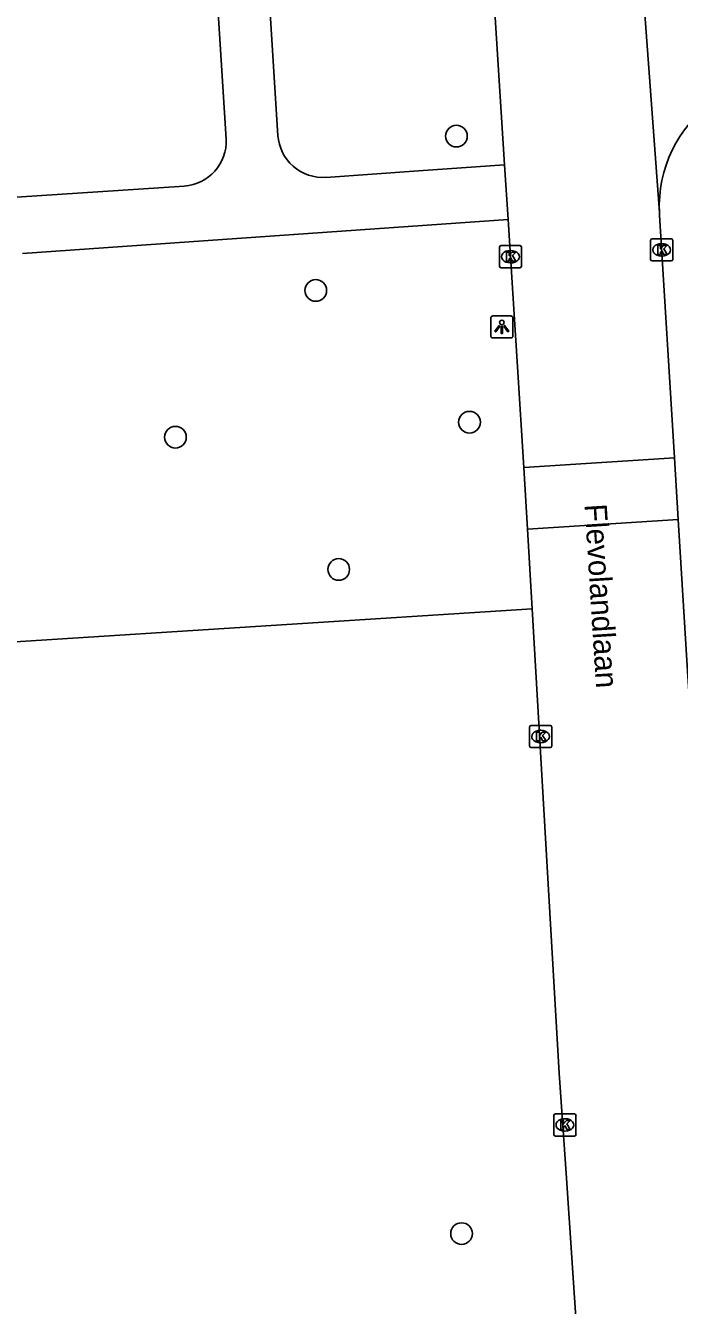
# Model space of a CAD drawing. Extents: x 159689 to 160786, y 387323 to 388339.
# Drawn here: x 160199.1 to 160228.6, y 387891.1 to 387948.8 of the extents above; entities that cross this region are included whole.
import ezdxf

# ---------------------------------------------------------------- set-up
doc = ezdxf.new("R2010")
doc.units = 0
for name, color, linetype in [('IMGEO_Boom', 7, 'Continuous'), ('IMGEO_Groenvoorziening', 7, 'Continuous'), ('IMGEO_Kolk', 7, 'Continuous'), ('IMGEO_Lichtpunt', 7, 'Continuous'), ('IMGEO_Openbare_ruimte_label', 7, 'Continuous'), ('IMGEO_Rijbaan_lokaal_open', 7, 'Continuous'), ('IMGEO_Voetpad_open', 7, 'Continuous')]:
    doc.layers.add(name, color=color, linetype=linetype)

msp = doc.modelspace()

# ---------------------------------------------------------------- linework, layer by layer
at = {"layer": 'IMGEO_Boom'}
for centre in [(160218.549, 387943.853), (160212.205, 387936.889), (160219.138, 387930.946), (160205.876, 387930.269), (160213.238, 387924.301), (160218.781, 387894.331)]:
    msp.add_circle(centre, 0.489, dxfattribs=at)
at = {"layer": 'IMGEO_Groenvoorziening'}
msp.add_lwpolyline([(160221.967, 387922.53), (160198.415, 387921.014), (160192.67, 387937.221)], dxfattribs=at)
at = {"layer": 'IMGEO_Kolk'}
for p, q in [((160227.379, 387939.219), (160228.231, 387939.219)), ((160220.484, 387937.987), (160220.484, 387938.839)), ((160220.559, 387938.913), (160221.411, 387938.913)), ((160220.972, 387938.693), (160220.997, 387938.693)), ((160221.485, 387938.839), (160221.485, 387937.987)), ((160227.304, 387938.293), (160227.304, 387939.145)), ((160227.792, 387938.999), (160227.817, 387938.999)), ((160228.305, 387939.145), (160228.305, 387938.293)), ((160220.995, 387938.133), (160220.97, 387938.133)), ((160228.231, 387938.219), (160227.379, 387938.219)), ((160227.815, 387938.439), (160227.79, 387938.439)), ((160221.411, 387937.913), (160220.559, 387937.913)), ((160221.919, 387917.262), (160222.771, 387917.262)), ((160221.844, 387916.336), (160221.844, 387917.188)), ((160222.332, 387917.042), (160222.357, 387917.042)), ((160222.845, 387917.188), (160222.845, 387916.336)), ((160222.771, 387916.262), (160221.919, 387916.262)), ((160222.355, 387916.482), (160222.33, 387916.482)), ((160222.94, 387898.81), (160222.94, 387899.662)), ((160223.015, 387899.736), (160223.867, 387899.736)), ((160223.428, 387899.516), (160223.453, 387899.516)), ((160223.941, 387899.662), (160223.941, 387898.81)), ((160223.867, 387898.736), (160223.015, 387898.736)), ((160223.451, 387898.956), (160223.426, 387898.956))]:
    msp.add_line(p, q, dxfattribs=at)
for points in [[(160227.379, 387939.219), (160228.231, 387939.219)], [(160220.484, 387937.987), (160220.484, 387938.839)], [(160220.559, 387938.913), (160221.411, 387938.913)], [(160220.805, 387938.613), (160220.928, 387938.613), (160220.928, 387938.462), (160221.058, 387938.613), (160221.222, 387938.613), (160221.076, 387938.462), (160221.229, 387938.213), (160221.077, 387938.213), (160220.992, 387938.377), (160220.928, 387938.31), (160220.928, 387938.213), (160220.805, 387938.213), (160220.805, 387938.613)], [(160221.485, 387938.839), (160221.485, 387937.987)], [(160227.304, 387938.293), (160227.304, 387939.145)], [(160227.625, 387938.919), (160227.748, 387938.919), (160227.748, 387938.768), (160227.878, 387938.919), (160228.042, 387938.919), (160227.896, 387938.768), (160228.049, 387938.519), (160227.897, 387938.519), (160227.812, 387938.683), (160227.748, 387938.616), (160227.748, 387938.519), (160227.625, 387938.519), (160227.625, 387938.919)], [(160228.305, 387939.145), (160228.305, 387938.293)], [(160228.231, 387938.219), (160227.379, 387938.219)], [(160221.411, 387937.913), (160220.559, 387937.913)], [(160221.919, 387917.262), (160222.771, 387917.262)], [(160221.844, 387916.336), (160221.844, 387917.188)], [(160222.165, 387916.962), (160222.288, 387916.962), (160222.288, 387916.811), (160222.418, 387916.962), (160222.582, 387916.962), (160222.436, 387916.811), (160222.589, 387916.562), (160222.437, 387916.562), (160222.352, 387916.726), (160222.288, 387916.659), (160222.288, 387916.562), (160222.165, 387916.562), (160222.165, 387916.962)], [(160222.845, 387917.188), (160222.845, 387916.336)], [(160222.771, 387916.262), (160221.919, 387916.262)], [(160222.94, 387898.81), (160222.94, 387899.662)], [(160223.015, 387899.736), (160223.867, 387899.736)], [(160223.261, 387899.436), (160223.384, 387899.436), (160223.384, 387899.285), (160223.514, 387899.436), (160223.678, 387899.436), (160223.532, 387899.285), (160223.685, 387899.036), (160223.533, 387899.036), (160223.448, 387899.2), (160223.384, 387899.133), (160223.384, 387899.036), (160223.261, 387899.036), (160223.261, 387899.436)], [(160223.941, 387899.662), (160223.941, 387898.81)], [(160223.867, 387898.736), (160223.015, 387898.736)]]:
    msp.add_lwpolyline(points, dxfattribs=at)
for centre, start, end in [((160227.381, 387939.143), 91.55205, 178.44795), ((160227.381, 387939.143), 91.55205, 178.44795), ((160228.229, 387939.143), 1.55205, 88.44795), ((160228.229, 387939.143), 1.55205, 88.44795), ((160220.561, 387938.837), 91.55205, 178.44795), ((160220.561, 387938.837), 91.55205, 178.44795), ((160221.409, 387938.837), 1.55205, 88.44795), ((160221.409, 387938.837), 1.55205, 88.44795), ((160227.381, 387938.295), 181.55205, 268.44795), ((160227.381, 387938.295), 181.55205, 268.44795), ((160228.229, 387938.295), 271.55205, 358.44795), ((160228.229, 387938.295), 271.55205, 358.44795), ((160220.561, 387937.989), 181.55205, 268.44795), ((160220.561, 387937.989), 181.55205, 268.44795), ((160221.409, 387937.989), 271.55205, 358.44795), ((160221.409, 387937.989), 271.55205, 358.44795), ((160221.921, 387917.186), 91.55205, 178.44795), ((160221.921, 387917.186), 91.55205, 178.44795), ((160222.769, 387917.186), 1.55205, 88.44795), ((160222.769, 387917.186), 1.55205, 88.44795), ((160221.921, 387916.338), 181.55205, 268.44795), ((160221.921, 387916.338), 181.55205, 268.44795), ((160222.769, 387916.338), 271.55205, 358.44795), ((160222.769, 387916.338), 271.55205, 358.44795), ((160223.017, 387899.66), 91.55205, 178.44795), ((160223.017, 387899.66), 91.55205, 178.44795), ((160223.865, 387899.66), 1.55205, 88.44795), ((160223.865, 387899.66), 1.55205, 88.44795), ((160223.017, 387898.812), 181.55205, 268.44795), ((160223.017, 387898.812), 181.55205, 268.44795), ((160223.865, 387898.812), 271.55205, 358.44795), ((160223.865, 387898.812), 271.55205, 358.44795)]:
    msp.add_arc(centre, 0.0765, start, end, dxfattribs=at)
for centre, major_axis, ratio, start_param, end_param in [((160220.971, 387938.413), (-0.387, 0.002), 0.722429, 4.712389, 7.853982), ((160220.996, 387938.413), (-0.39, 0.002), 0.717154, 1.570796, 4.712389), ((160227.791, 387938.719), (-0.387, 0.002), 0.722429, 4.712389, 7.853982), ((160227.816, 387938.719), (-0.39, 0.002), 0.717154, 1.570796, 4.712389), ((160222.331, 387916.762), (-0.387, 0.002), 0.722429, 4.712389, 7.853982), ((160222.356, 387916.762), (-0.39, 0.002), 0.717154, 1.570796, 4.712389), ((160223.427, 387899.236), (-0.387, 0.002), 0.722429, 4.712389, 7.853982), ((160223.452, 387899.236), (-0.39, 0.002), 0.717154, 1.570796, 4.712389)]:
    msp.add_ellipse(centre, major_axis=major_axis, ratio=ratio, start_param=start_param, end_param=end_param, dxfattribs=at)
at = {"layer": 'IMGEO_Lichtpunt'}
for p, q in [((160220.999, 387935.742), (160220.191, 387935.742)), ((160220.999, 387935.742), (160220.191, 387935.742)), ((160220.097, 387935.647), (160220.097, 387934.84)), ((160220.097, 387935.647), (160220.097, 387934.84)), ((160221.093, 387934.84), (160221.093, 387935.647)), ((160221.093, 387934.84), (160221.093, 387935.647)), ((160220.191, 387934.746), (160220.999, 387934.746)), ((160220.191, 387934.746), (160220.999, 387934.746))]:
    msp.add_line(p, q, dxfattribs=at)
for points in [[(160220.471, 387935.311), (160220.51, 387935.283), (160220.322, 387935.021), (160220.284, 387935.048), (160220.471, 387935.311)], [(160220.573, 387935.263), (160220.62, 387935.263), (160220.62, 387934.941), (160220.573, 387934.941), (160220.573, 387935.263)], [(160220.683, 387935.283), (160220.721, 387935.31), (160220.908, 387935.048), (160220.869, 387935.02), (160220.683, 387935.283)]]:
    msp.add_lwpolyline(points, dxfattribs=at)
msp.add_circle((160220.596, 387935.445), 0.0994, dxfattribs=at)
for centre, start, end in [((160220.191, 387935.647), 90, 180), ((160220.191, 387935.647), 90, 180), ((160220.999, 387935.647), 0, 90), ((160220.999, 387935.647), 0, 90), ((160220.191, 387934.84), 180, 270), ((160220.191, 387934.84), 180, 270), ((160220.999, 387934.84), 270, 0), ((160220.999, 387934.84), 270, 360)]:
    msp.add_arc(centre, 0.0946, start, end, dxfattribs=at)
at = {"layer": 'IMGEO_Rijbaan_lokaal_open'}
for points in [[(160220.722, 387942.558), (160218.682, 387974.632), (160217.994, 387985.826)], [(160226.342, 387958.942), (160227.701, 387940.407)], [(160220.879, 387940.086), (160220.722, 387942.558)], [(160228.383, 387929.335), (160227.707, 387940.29), (160227.701, 387940.407)], [(160221.586, 387928.904), (160221.302, 387933.442), (160220.879, 387940.086)], [(160228.383, 387929.335), (160221.586, 387928.904)], [(160228.555, 387926.551), (160228.383, 387929.335)], [(160221.76, 387926.12), (160221.586, 387928.904)], [(160221.76, 387926.12), (160228.555, 387926.551)], [(160230.401, 387898.277), (160228.977, 387919.718), (160228.555, 387926.551)], [(160221.967, 387922.53), (160221.76, 387926.12)], [(160224.487, 387882.226), (160223.514, 387896.832), (160223.178, 387901.569), (160221.967, 387922.53)]]:
    msp.add_lwpolyline(points, dxfattribs=at)
msp.add_arc((160233.599, 387940.653), 5.903, 126.21786, 182.38562, dxfattribs=at)
at = {"layer": 'IMGEO_Voetpad_open'}
for points in [[(160206.899, 388001.555), (160206.996, 388000), (160207.119, 387998.051), (160208.215, 387980.475), (160208.411, 387977.333), (160210.498, 387943.887)], [(160208.168, 387943.723), (160207.556, 387953.24)], [(160212.662, 387941.993), (160216.836, 387942.285), (160220.722, 387942.558)], [(160198.713, 387941.098), (160206.269, 387941.601)], [(160220.879, 387940.086), (160198.981, 387938.557)]]:
    msp.add_lwpolyline(points, dxfattribs=at)
for centre, radius, start, end in [((160212.521, 387944.016), 2.027, 183.63553, 273.97762), ((160206.133, 387943.633), 2.037, 273.82156, 2.52705)]:
    msp.add_arc(centre, radius, start, end, dxfattribs=at)

# ---------------------------------------------------------------- texts
at = {"layer": 'IMGEO_Openbare_ruimte_label'}
msp.add_text('Flevolandlaan', height=1, rotation=273.61207, dxfattribs=at).set_placement((160224.325, 387927.231))

doc.saveas('drawing.dxf')
